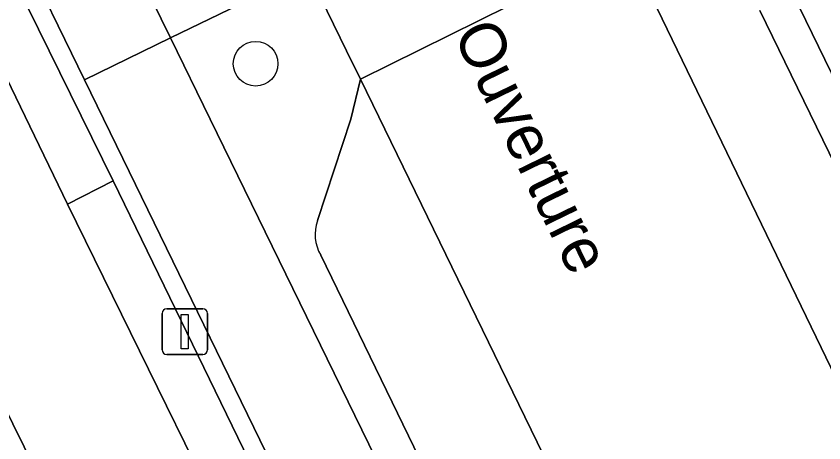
# Model space of a CAD drawing. Extents: x 160455 to 162082, y 388339 to 389736.
# Drawn here: x 160965.73 to 160983.41, y 388845.86 to 388855.2 of the extents above; entities that cross this region are included whole.
import ezdxf

# ---------------------------------------------------------------- set-up
doc = ezdxf.new("R2010")
doc.units = 0
for name, color, linetype in [('IMGEO_Boom', 7, 'Continuous'), ('IMGEO_Fietspad_gesloten', 7, 'Continuous'), ('IMGEO_Lichtmast', 7, 'Continuous'), ('IMGEO_Openbare_ruimte_label', 7, 'Continuous'), ('IMGEO_Parkeervlak_open', 7, 'Continuous'), ('IMGEO_Rijbaan_lokaal_gesloten', 7, 'Continuous'), ('IMGEO_Verkeerseiland_open', 7, 'Continuous'), ('IMGEO_Voetpad_gesloten', 7, 'Continuous'), ('IMGEO_Voetpad_open', 7, 'Continuous')]:
    doc.layers.add(name, color=color, linetype=linetype)

msp = doc.modelspace()

# ---------------------------------------------------------------- linework, layer by layer
at = {"layer": 'IMGEO_Boom'}
msp.add_circle((160970.973, 388854.162), 0.489, dxfattribs=at)
at = {"layer": 'IMGEO_Fietspad_gesloten'}
for points in [[(161021.707, 388780.587), (161021.087, 388781.853), (161018.227, 388787.693), (161016.943, 388790.314), (161000, 388824.949), (160994.813, 388835.553), (160994.337, 388836.526), (160982.346, 388861.167), (160980.503, 388860.271), (160992.497, 388835.627), (160992.974, 388834.647), (161000, 388820.255), (161015.023, 388789.483), (161016.354, 388786.762), (161019.198, 388780.947), (161021.279, 388776.693), (161023.304, 388772.58), (161023.771, 388771.668), (161024.41, 388770.383), (161025.995, 388771.182)], [(160981.143, 388830.068), (160969.977, 388852.944), (160969.108, 388854.725), (160967.226, 388853.81), (160968.207, 388851.798), (160979.24, 388829.116)]]:
    msp.add_lwpolyline(points, dxfattribs=at)
at = {"layer": 'IMGEO_Lichtmast'}
for p, q in [((160968.926, 388847.894), (160968.926, 388848.694)), ((160968.926, 388848.694), (160968.926, 388847.894)), ((160969.026, 388848.794), (160969.816, 388848.794)), ((160969.816, 388848.794), (160969.026, 388848.794)), ((160969.916, 388848.694), (160969.916, 388847.894)), ((160969.916, 388847.894), (160969.916, 388848.694)), ((160969.816, 388847.794), (160969.026, 388847.794)), ((160969.026, 388847.794), (160969.816, 388847.794))]:
    msp.add_line(p, q, dxfattribs=at)
msp.add_lwpolyline([(160969.346, 388848.669), (160969.496, 388848.669), (160969.496, 388847.919), (160969.346, 388847.919), (160969.346, 388848.669)], dxfattribs=at)
for centre, start, end in [((160969.026, 388848.694), 90, 180), ((160969.026, 388848.694), 90, 180), ((160969.816, 388848.694), 0, 90), ((160969.816, 388848.694), 360, 90), ((160969.026, 388847.894), 180, 270), ((160969.026, 388847.894), 180, 270), ((160969.816, 388847.894), 270, 0), ((160969.816, 388847.894), 270, 0)]:
    msp.add_arc(centre, 0.1, start, end, dxfattribs=at)
at = {"layer": 'IMGEO_Parkeervlak_open'}
for points in [[(160981.435, 388855.804), (160979.981, 388856.335), (160979.112, 388856.719), (160984.865, 388844.805), (160993.848, 388826.468), (161000, 388813.8), (161002.577, 388808.494)], [(161003.016, 388812.13), (161000, 388818.304), (160992.207, 388834.257), (160991.785, 388835.246), (160982.005, 388855.326)], [(160996.539, 388806.059), (160995.313, 388808.673), (160987.843, 388823.92), (160979.536, 388840.94), (160973.268, 388853.82), (160973.057, 388852.946), (160972.324, 388850.724)], [(160972.397, 388849.97), (160981.87, 388830.442), (160982.341, 388829.49), (160992.665, 388808.222)]]:
    msp.add_lwpolyline(points, dxfattribs=at)
msp.add_arc((160973.17, 388850.425), 0.897, 160.5552, 210.5048, dxfattribs=at)
at = {"layer": 'IMGEO_Rijbaan_lokaal_gesloten'}
msp.add_lwpolyline([(160979.112, 388856.719), (160978.929, 388857.097), (160978.818, 388857.327), (160977.973, 388859.04), (160972.117, 388856.19), (160972.964, 388854.444), (160973.268, 388853.82)], close=True, dxfattribs=at)
msp.add_lwpolyline([(160993.848, 388826.468), (160984.865, 388844.805), (160979.112, 388856.719), (160973.268, 388853.82), (160979.536, 388840.94), (160987.843, 388823.92)], dxfattribs=at)
at = {"layer": 'IMGEO_Verkeerseiland_open'}
for points in [[(160982.005, 388855.326), (160991.785, 388835.246), (160992.497, 388835.627), (160980.503, 388860.271)], [(160973.268, 388853.82), (160972.964, 388854.444), (160972.117, 388856.19), (160969.108, 388854.725), (160969.977, 388852.944), (160981.143, 388830.068), (160981.87, 388830.442), (160972.397, 388849.97)], [(160972.324, 388850.724), (160973.057, 388852.946), (160973.268, 388853.82)]]:
    msp.add_lwpolyline(points, dxfattribs=at)
msp.add_arc((160973.17, 388850.425), 0.897, 160.5552, 210.5048, dxfattribs=at)
at = {"layer": 'IMGEO_Voetpad_gesloten'}
msp.add_lwpolyline([(160967.666, 388857.68), (160965.786, 388856.765), (160967.226, 388853.81), (160969.108, 388854.725)], close=True, dxfattribs=at)
at = {"layer": 'IMGEO_Voetpad_open'}
for points in [[(160947.014, 388884.131), (160951.4, 388886.278), (160945.5, 388898.364), (160943.082, 388897.181), (160948.262, 388886.604), (160945.527, 388885.278), (160946.404, 388883.487), (160959.714, 388856.328), (160962.843, 388849.98), (160968.804, 388837.789), (160969.631, 388838.199)], [(160968.207, 388851.798), (160967.226, 388853.81), (160965.786, 388856.765), (160954.001, 388880.949), (160953.626, 388880.772), (160955.917, 388876.08), (160957.838, 388872.115), (160956.869, 388871.643), (160958.323, 388868.654), (160959.297, 388869.127), (160961.258, 388865.103), (160963.876, 388859.674), (160967.853, 388851.597), (160972.565, 388841.887), (160978.889, 388828.943), (160979.24, 388829.116)], [(160966.856, 388851.087), (160967.853, 388851.597), (160963.876, 388859.674), (160962.94, 388859.194)], [(160970.682, 388859.148), (160967.666, 388857.68), (160969.108, 388854.725), (160972.117, 388856.19)], [(160966.856, 388851.087), (160971.593, 388841.435), (160972.565, 388841.887), (160967.853, 388851.597)]]:
    msp.add_lwpolyline(points, close=True, dxfattribs=at)
msp.add_lwpolyline([(160978.413, 388827.493), (160971.593, 388841.435), (160966.856, 388851.087), (160962.94, 388859.194), (160960.29, 388864.629), (160958.323, 388868.654), (160956.869, 388871.643), (160954.941, 388875.6), (160952.64, 388880.307), (160952.119, 388881.376), (160953.466, 388882.047), (160951.4, 388886.278), (160947.014, 388884.131), (160969.631, 388838.199), (160972.262, 388839.513), (160994.015, 388795.086)], dxfattribs=at)

# ---------------------------------------------------------------- texts
at = {"layer": 'IMGEO_Openbare_ruimte_label'}
msp.add_text('Ouverture', height=1, rotation=295.9757, dxfattribs=at).set_placement((160975.282, 388854.811))

doc.saveas('drawing.dxf')
